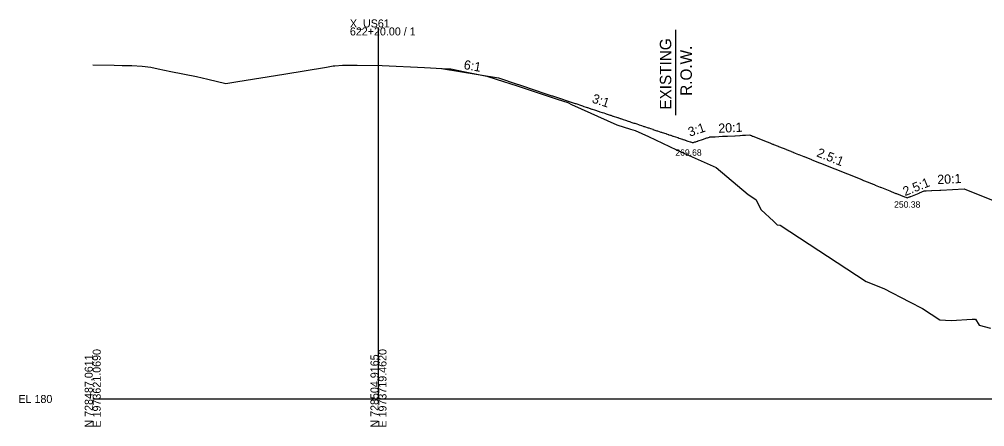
# Model space of a CAD drawing. Extents: x -26 to 1629, y -25 to 9635.
# Drawn here: x -25.7 to 312.2, y 5490.3 to 5632.8 of the extents above; entities that cross this region are included whole.
import ezdxf

# ---------------------------------------------------------------- set-up
doc = ezdxf.new("R2010")
doc.units = 0
for name, color, linetype in [('Default', 7, 'Continuous'), ('Draft_XS_Grid', 7, 'Continuous'), ('DTM CONTOURS_MAJOR', 7, 'Continuous'), ('DTM_X_GROUND', 7, 'Continuous'), ('XS_CELL', 7, 'Continuous'), ('XS_P_GROUND', 7, 'Continuous'), ('XS_P_TX_DCH', 7, 'Continuous'), ('XS_P_TX_FS_BS', 7, 'Continuous'), ('XS_X_ROW', 7, 'Continuous')]:
    doc.layers.add(name, color=color, linetype=linetype)

msp = doc.modelspace()

# ---------------------------------------------------------------- linework, layer by layer
at = {"layer": 'DTM_X_GROUND'}
msp.add_lwpolyline([(0, 5616.93), (7.5, 5616.78), (10.29, 5616.72), (13.13, 5616.67), (13.74, 5616.64), (17.26, 5616.5), (20.38, 5616.09), (22.85, 5615.46), (27.36, 5614.62), (36.26, 5612.79), (40.28, 5611.88), (46.61, 5610.44), (50.73, 5611.1), (66.88, 5613.62), (81.77, 5616.15), (84.12, 5616.53), (84.77, 5616.59), (87.43, 5616.8), (92.58, 5616.75), (101.35, 5616.65), (116.12, 5615.96), (122.27, 5615.67), (124.74, 5615.53), (125.33, 5615.5), (130.3, 5614.49), (137.97, 5612.91), (141.24, 5611.93), (148.48, 5609.53), (162.58, 5604.95), (166.31, 5603.74), (167.52, 5603.08), (183.43, 5595.94), (188.16, 5594.38), (189.87, 5593.92), (194.54, 5591.89), (204.31, 5587.12), (206.58, 5586.1), (218.16, 5581), (229.43, 5571.6), (232.04, 5569.74), (233.95, 5566.19), (238.19, 5562.2), (239.56, 5560.98), (240.59, 5560.84), (270.72, 5541.08), (276.89, 5538.69), (285.8, 5534.05), (290.42, 5531.64), (296.41, 5527.7), (300.47, 5527.51), (307.8, 5527.96), (308.96, 5527.98), (310.23, 5525.82), (314.24, 5524.82)], dxfattribs=at)
at = {"layer": 'XS_CELL'}
for p, q in [((100, 5500), (100, 5630)), ((0, 5500), (100, 5500)), ((100, 5500), (550, 5500))]:
    msp.add_line(p, q, dxfattribs=at)
at = {"layer": 'XS_P_GROUND'}
for points in [[(122, 5615.68), (142, 5612.35)], [(142, 5612.35), (145.19, 5611.29), (145.38, 5611.22), (152.2, 5608.95), (152.38, 5608.89), (160.72, 5606.11), (160.93, 5606.04), (168.82, 5603.41), (169.03, 5603.34), (171.09, 5602.65), (171.48, 5602.52), (171.5, 5602.51), (173.04, 5602), (173.12, 5601.98), (174.69, 5601.45), (174.74, 5601.43), (174.76, 5601.43), (175.55, 5601.16), (175.59, 5601.15), (177.18, 5600.62), (177.22, 5600.61), (177.51, 5600.51), (178.29, 5600.25), (178.81, 5600.08), (179.46, 5599.86), (179.63, 5599.81), (181.12, 5599.31), (181.27, 5599.26), (182.05, 5599), (182.09, 5598.99), (183.67, 5598.46), (183.73, 5598.44), (183.75, 5598.43), (184.55, 5598.16), (184.56, 5598.16), (184.66, 5598.13), (184.68, 5598.12), (185.38, 5597.89), (185.38, 5597.89), (185.43, 5597.87), (185.69, 5597.78), (186.49, 5597.52), (187.44, 5597.2), (187.8, 5597.08), (187.86, 5597.06), (187.93, 5597.04), (188.08, 5596.99), (188.7, 5596.78), (189.37, 5596.56), (189.68, 5596.46), (190.37, 5596.22), (190.99, 5596.02), (191.27, 5595.92), (192.05, 5595.66), (192.61, 5595.48), (192.87, 5595.39), (192.9, 5595.38), (193.13, 5595.31), (194.33, 5594.9), (194.46, 5594.86), (194.58, 5594.82), (195.17, 5594.62), (195.97, 5594.36), (196.05, 5594.33), (197.12, 5593.98), (197.45, 5593.87), (197.65, 5593.8), (198.82, 5593.41), (199.06, 5593.33), (199.24, 5593.27), (200.52, 5592.84), (200.66, 5592.79), (200.83, 5592.74), (201.37, 5592.56), (201.45, 5592.53), (201.63, 5592.47), (202.22, 5592.27), (202.26, 5592.26), (203.02, 5592.01), (203.09, 5591.99), (203.93, 5591.7), (203.97, 5591.69), (204, 5591.68), (204.71, 5591.44), (204.79, 5591.42), (204.96, 5591.36), (205.13, 5591.3), (206.35, 5590.9), (206.49, 5590.85), (206.5, 5590.85), (206.53, 5590.84), (207.07, 5590.66), (207.17, 5590.62), (207.36, 5590.56), (208.28, 5590.26), (209.05, 5590), (209.08, 5589.99), (209.21, 5589.95), (209.94, 5589.7), (209.97, 5589.69), (210, 5589.68), (210.72, 5589.92), (210.81, 5589.95), (211.04, 5590.03), (211.24, 5590.1), (211.67, 5590.24), (211.74, 5590.26), (211.92, 5590.32), (213.4, 5590.82), (214.97, 5591.34), (215.14, 5591.39), (215.87, 5591.64), (216, 5591.68), (216.01, 5591.68), (216.27, 5591.7), (217.72, 5591.77), (217.75, 5591.77), (217.81, 5591.77), (220.37, 5591.9), (220.41, 5591.9), (222.12, 5591.99), (222.18, 5591.99), (224.75, 5592.12), (224.8, 5592.12), (226.52, 5592.21), (226.54, 5592.21), (227.4, 5592.25), (227.46, 5592.26), (228.41, 5592.3), (230, 5592.38), (230.05, 5592.36), (230.6, 5592.14), (230.94, 5592.01), (231.01, 5591.98), (233.64, 5590.93), (233.66, 5590.92), (234.5, 5590.58), (234.5, 5590.58), (234.52, 5590.57), (234.54, 5590.57), (235.39, 5590.23), (235.43, 5590.21), (235.69, 5590.1), (236.36, 5589.84), (237.18, 5589.51), (237.18, 5589.51), (237.92, 5589.21), (238.07, 5589.15), (238.25, 5589.08), (239.84, 5588.45), (239.87, 5588.44), (239.97, 5588.39), (241.62, 5587.73), (241.66, 5587.72), (242.51, 5587.38), (242.57, 5587.36), (242.63, 5587.33), (244.3, 5586.66), (244.37, 5586.63), (245.16, 5586.32), (245.19, 5586.3), (245.24, 5586.28), (246.99, 5585.59), (247.09, 5585.55), (247.13, 5585.53), (248.9, 5584.82), (248.97, 5584.79), (251.49, 5583.78), (251.49, 5583.78), (251.63, 5583.73), (251.7, 5583.7), (254.38, 5582.63), (254.74, 5582.49), (269.11, 5576.74), (269.18, 5576.71), (271.9, 5575.62), (271.92, 5575.61), (272.83, 5575.25), (272.85, 5575.24), (273.76, 5574.88), (273.81, 5574.86), (275.63, 5574.13), (275.72, 5574.09), (275.99, 5573.98), (279, 5572.78), (279.38, 5572.63), (281.08, 5571.95), (281.26, 5571.88), (281.33, 5571.85), (284.1, 5570.74), (284.12, 5570.73), (284.55, 5570.56), (285, 5570.38), (285.05, 5570.4), (285.54, 5570.6), (285.99, 5570.78), (286.05, 5570.8), (286.25, 5570.88), (289.23, 5572.07), (289.37, 5572.13), (291, 5572.78), (291.71, 5572.82), (293.52, 5572.91), (293.63, 5572.91), (293.7, 5572.92), (296.51, 5573.06), (296.76, 5573.07), (305, 5573.48), (343.03, 5558.27)]]:
    msp.add_lwpolyline(points, dxfattribs=at)
at = {"layer": 'XS_X_ROW'}
msp.add_line((204, 5629.17), (204, 5599.27), dxfattribs=at)

# ---------------------------------------------------------------- texts
at = {"layer": 'Default'}
msp.add_text('X', height=0.12, dxfattribs=at).set_placement((141.96, 5612.29))
at = {"layer": 'Draft_XS_Grid'}
msp.add_text('-', height=0.0001, dxfattribs=at).set_placement((0, 5500))
at = {"layer": 'DTM CONTOURS_MAJOR'}
for p in [(121.96, 5615.62), (141.96, 5612.29), (203.96, 5591.62), (215.96, 5591.62), (229.96, 5592.32), (209.96, 5589.62), (278.96, 5572.72), (290.96, 5572.72), (304.96, 5573.42), (284.96, 5570.32)]:
    msp.add_text('X', height=0.12, dxfattribs=at).set_placement(p)
at = {"layer": 'XS_CELL'}
for s, p in [('X_US61', (90, 5630)), ('622+20.00 / 1', (90, 5627.2)), ('EL 180', (-26, 5498.6))]:
    msp.add_text(s, height=2.8, dxfattribs=at).set_placement(p)
for s, p in [('E 1973621.0690', (2.8, 5490)), ('E 1973719.4620', (102.8, 5490)), ('N 728487.0611', (0, 5490)), ('N 728504.9165', (100, 5490))]:
    msp.add_text(s, height=2.8, rotation=90, dxfattribs=at).set_placement(p)
at = {"layer": 'XS_P_TX_DCH'}
for s, p in [('269.68', (203.9, 5585.09)), ('250.38', (280.44, 5566.93))]:
    msp.add_text(s, height=2.25, dxfattribs=at).set_placement(p)
at = {"layer": 'XS_P_TX_FS_BS'}
for s, rotation, p in [('6:1', 350.5377, (129.68, 5615.45)), ('3:1', 341.5651, (174.49, 5603.8)), ('3:1', 18.4349, (208.96, 5591.74)), ('20:1', 2.8624, (219.02, 5593.09)), ('2.5:1', 338.1986, (253.09, 5584.96)), ('20:1', 2.8624, (295.65, 5575.16)), ('2.5:1', 21.8014, (284.29, 5570.95))]:
    msp.add_text(s, height=3.24, rotation=rotation, dxfattribs=at).set_placement(p)
at = {"layer": 'XS_X_ROW'}
for s, p in [('EXISTING', (202.47, 5601.23)), ('R.O.W.', (209.67, 5606.08))]:
    msp.add_text(s, height=4, rotation=90, dxfattribs=at).set_placement(p)

doc.saveas('drawing.dxf')
